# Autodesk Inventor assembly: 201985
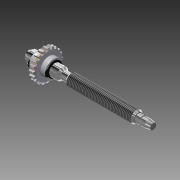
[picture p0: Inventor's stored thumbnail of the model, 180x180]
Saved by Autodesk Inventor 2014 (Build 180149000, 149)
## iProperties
Created: 2007-12
Part Number: 201985
Document SubType Name: Assembly
Designer: MM
Mass: 109.117 g
Surface Area: 82.6289 cm^2
Volume: 17.355 cm^3
Density: 6.28739 g/cm^3
Description: BALL SCREW SHAFT ASSEMBLY
Component Category: Lower Component
Author: MM
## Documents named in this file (4)
- C:\Users\iTools\Desktop\tutorial files\Automotive\2000\201985.iam
- C:\Users\iTools\Desktop\tutorial files\Automotive\2000\201351.ipt
- C:\Users\iTools\Desktop\tutorial files\Automotive\2000\200771.ipt
- C:\Users\iTools\Desktop\tutorial files\Automotive\8000\800985.ipt
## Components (4 placed, 3 different names)
1. Worm Gear:1 — Mate:1, Angle:1, Flush:1, Insert:1, Insert:3, Mate:2
2. Shaft:1 — Mate:1, Angle:1, Flush:1, Insert:2, Angle:2, Angle:3, Insert:3, Mate:2
3. JIS B 2804 12x1:1 — Insert:1, Angle:3
4. JIS B 2804 12x1:2 — Insert:2, Angle:2
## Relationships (9: Angle 3, Insert 3, Mate 2, Flush 1)
- Mate:1: Worm Gear:1 ↔ Shaft:1
- Angle:1: Worm Gear:1 ↔ Shaft:1
- Flush:1: Worm Gear:1 ↔ Shaft:1
- Insert:1: Worm Gear:1 ↔ JIS B 2804 12x1:1
- Insert:2: Shaft:1 ↔ JIS B 2804 12x1:2
- Angle:2: Shaft:1 ↔ JIS B 2804 12x1:2
- Angle:3: Shaft:1 ↔ JIS B 2804 12x1:1
- Insert:3: Worm Gear:1 ↔ Shaft:1
- Mate:2: Worm Gear:1 ↔ Shaft:1
